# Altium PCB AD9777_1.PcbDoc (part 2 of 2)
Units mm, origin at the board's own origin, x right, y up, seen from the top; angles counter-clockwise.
Board outline 148.59 x 134.62 mm, 4 copper layers (Top Layer, Ground, POwer, Bottom Layer), stack 0.778 mm thick; 277 components, 168 nets, 827 pads, 113 vias.
Unrouted connection lines stored in the file: 4.
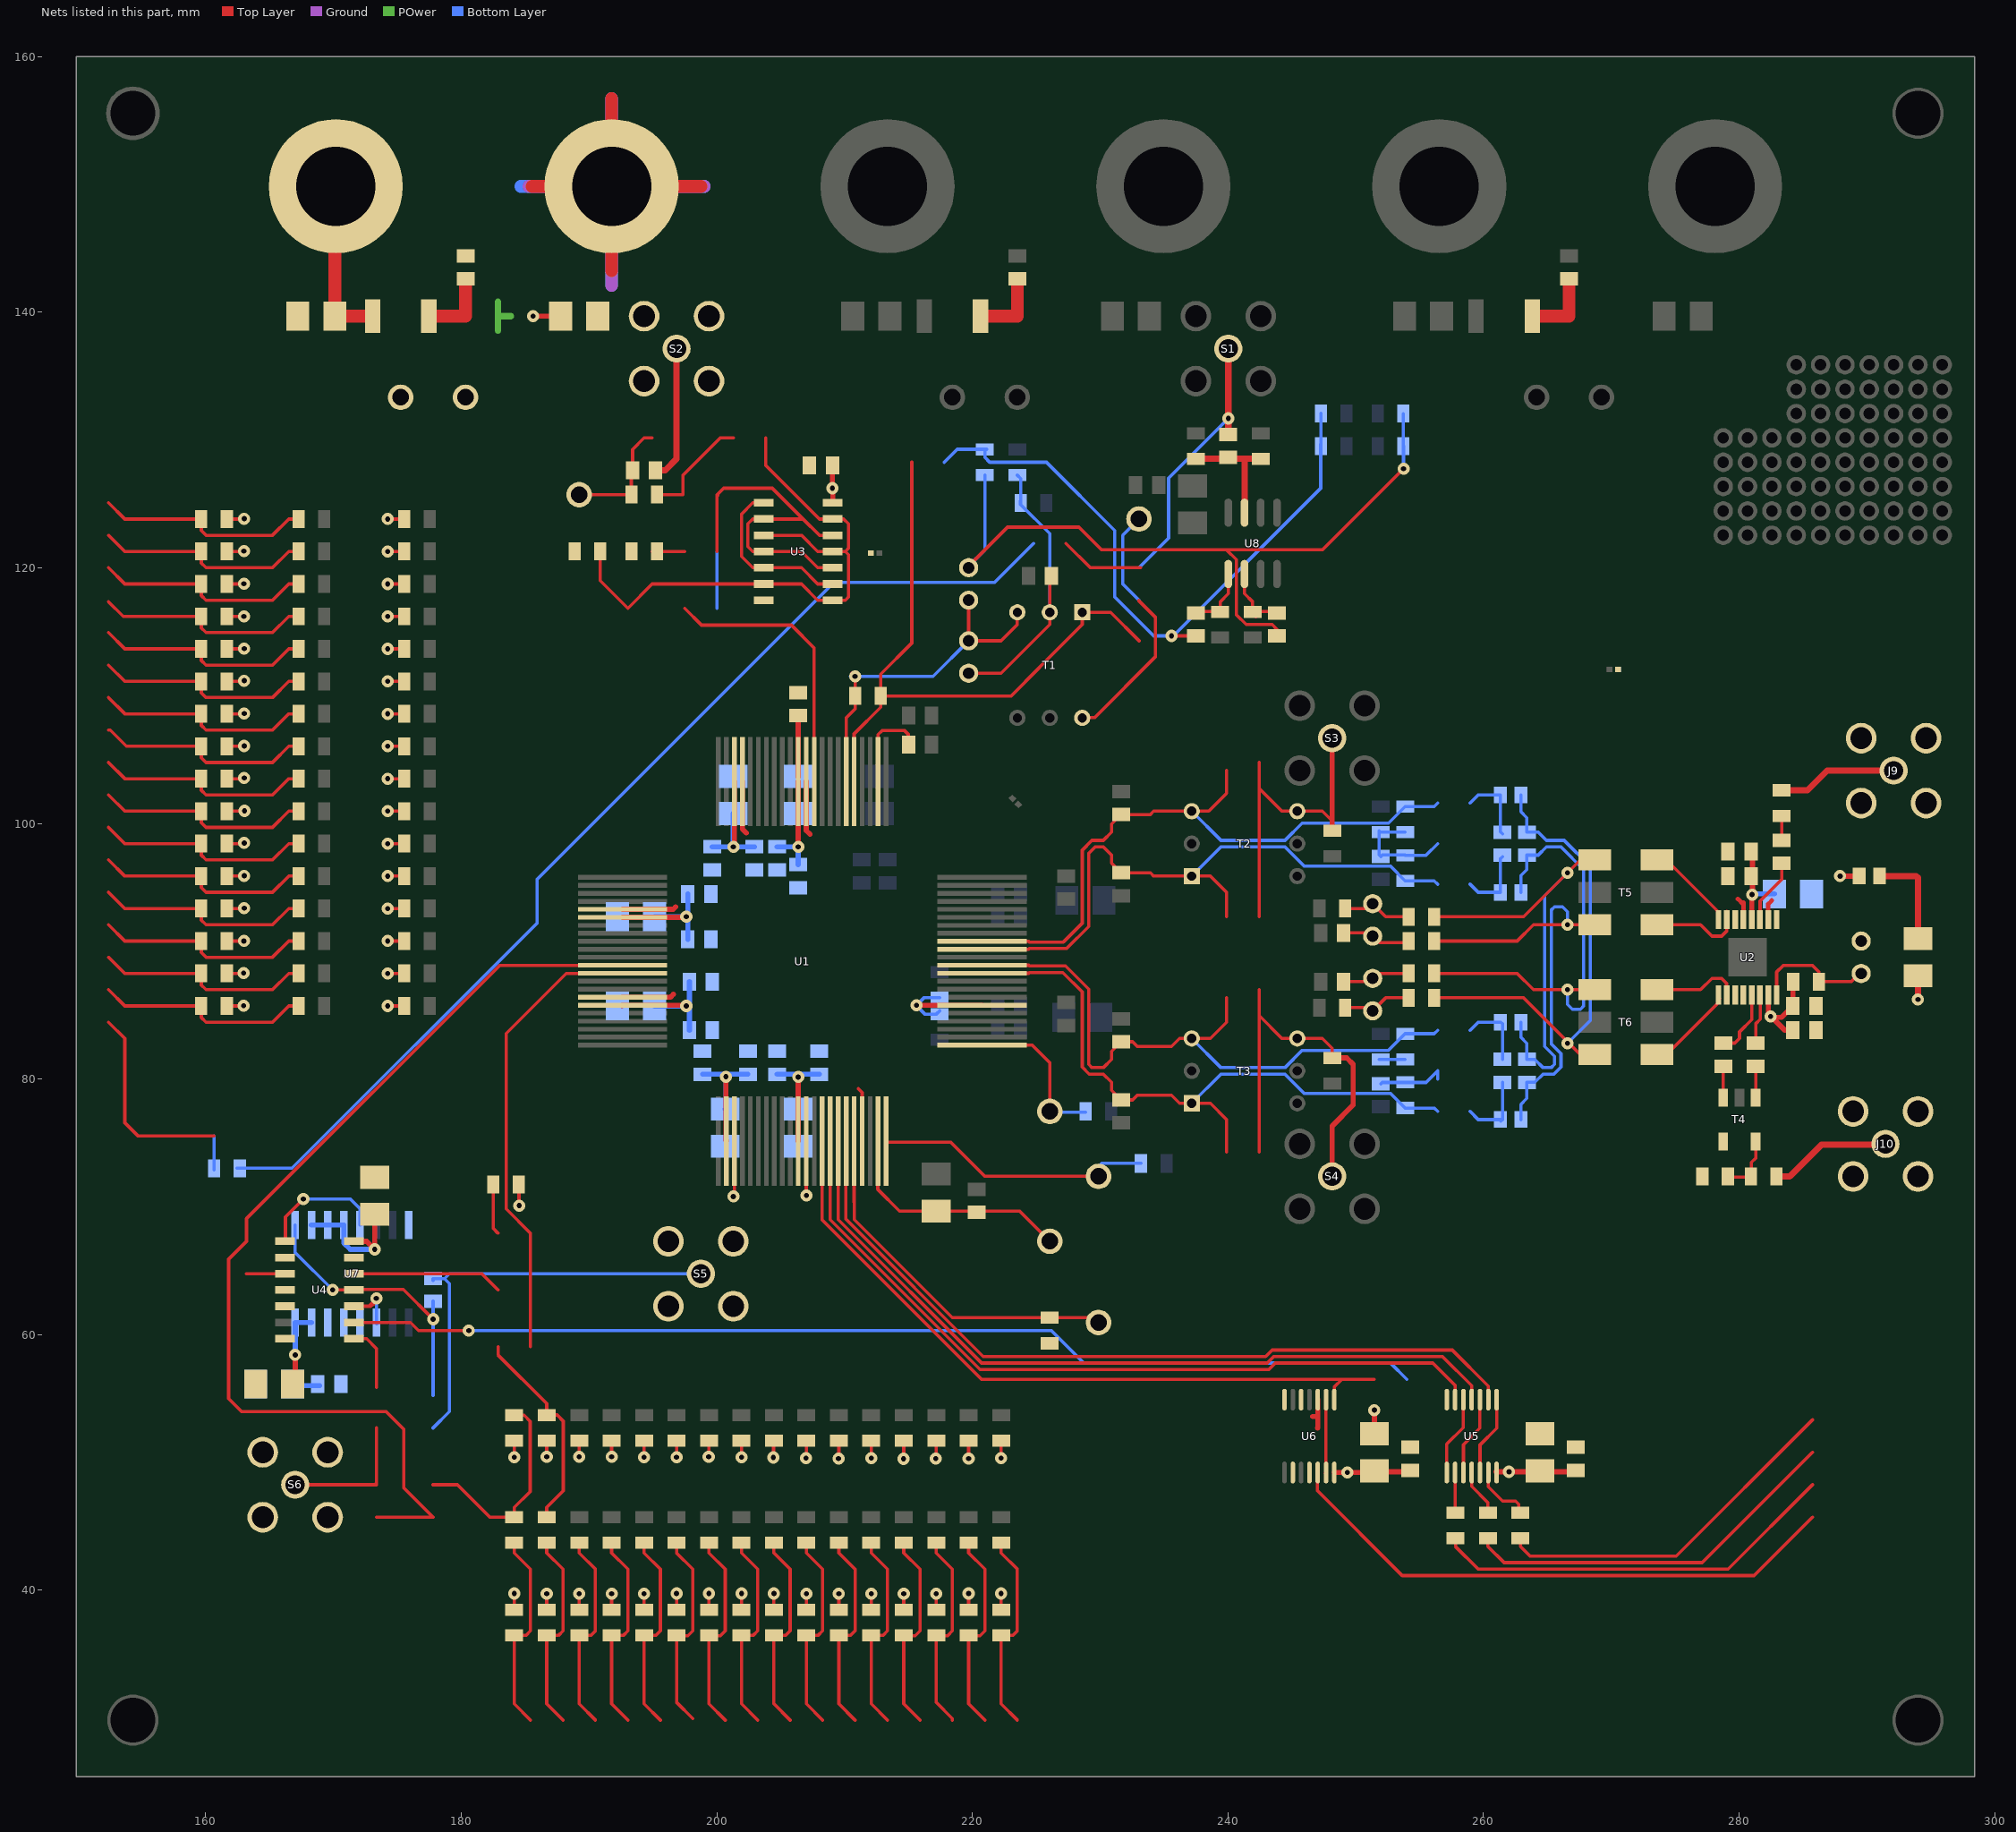
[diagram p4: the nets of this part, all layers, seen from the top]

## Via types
v1: diameter 0.95, hole 0.4, Top Layer to Bottom Layer, 112 vias
v2: diameter 0.95, hole 0.4, Top Layer to Bottom Layer, tented bottom, 1 vias

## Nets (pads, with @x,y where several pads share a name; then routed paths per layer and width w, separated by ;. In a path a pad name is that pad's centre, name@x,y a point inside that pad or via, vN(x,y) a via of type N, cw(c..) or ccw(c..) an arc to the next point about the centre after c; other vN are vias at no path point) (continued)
DGND: C5.2 C6.2 C7.2 C8.2 C9.2 C10.2 C21.2 C22.2 C23.2 C24.2 C25.2 C26.2 C30.2@173.228,72.316 C31.2 C33.2 C34.2 C36.2 C37.2 C38.2 C39.2 C40.2 C41.2 C43.2 C44.2 C50.1 C51.1 C52.2 C53.2 C65.2 C66.2 C67.2 J5.1 JP44.1 R6.1 R13.1@161.655,123.825 R14.1@161.655,121.285 R18.1@161.655,118.745 R25.1 R27.1 R29.1 R31.1 R38.1 R39.2 R40.1 R41.1 R44.1 R46.1 R47.1 R49.1 R51.1 R52.1 R53.1 R54.1 R55.2 R56.2 R57.2 R58.2 R59.2 R60.2 R61.2 R62.2 R63.2 R64.2 R65.2 R66.2 R67.2 R68.2 R69.2 R70.2 R71.1 R72.1 R73.1 R74.1 R75.1 R76.1 R77.1 R78.1 R79.1 R80.1 R81.1 R82.1 R83.1 R84.1 R85.1 R86.1 R90.2 R91.2 R92.2 R93.2 R94.2 R95.2 R96.2 R97.2 R98.2 R99.2 R100.2 R101.2 R102.2 R103.2 R104.2 R105.2 S2.2 S5.2 S6.2 TP3.1 U1.11 U1.19 U1.27 U1.38 U1.47 U1.56 U1.63 U3.7 U4.2 U4.4 U4.5 U4.7 U4.10 U4.13 U5.7 U6.3 U6.5 U6.7 U6.9 U6.11 U7.8 U7.11 U7.12 U7.13 U7.14 | length 209.2
  Top Layer w0.254: R62.2@161.655,85.725 162.966,85.725 v1(162.966,85.75) ; R61.2@161.655,88.265 v1@162.941,88.265 ; R60.2@161.655,90.805 v1(162.992,90.805) ; R59.2@161.655,93.345 v1@162.992,93.345 ; R58.2@161.655,95.885 162.992,95.885 v1(163.017,95.91) ; R57.2@161.655,98.425 162.966,98.425 v1(163.017,98.476) ; R56.2@161.655,100.965 163.017,100.965 v1(163.043,100.99) ; R55.2@161.655,103.505 162.966,103.505 v1(163.017,103.556) ; R41.1@161.655,106.045 162.992,106.045 v1(163.017,106.07) ; R31.1@161.655,108.585 162.992,108.585 v1(163.017,108.61) ; R29.1@161.655,111.125 163.017,111.125 v1(163.017,111.176) ; R27.1@161.655,113.665 162.992,113.665 v1(163.017,113.69) ; R25.1@161.655,116.205 v1(162.992,116.205) ; R18.1@161.655,118.745 162.966,118.745 v1(162.992,118.77) ; R14.1@161.655,121.285 162.966,121.285 v1(162.992,121.31) ; R13.1@161.655,123.825 162.992,123.825 v1(163.017,123.85) ; U4.10@171.602,62.255 172.771,62.255 v1(173.355,62.84) ; U4.10@171.61,62.23 172.898,62.23 172.98,62.313 173.057,62.313 ; 173.145,62.401 173.145,62.478 v1@173.317,62.649 ; v1(174.244,85.725) R70.2@175.53,85.725 ; v1(174.244,88.265) R69.2@175.53,88.265 ; v1(174.244,90.805) R68.2@175.53,90.805 ; v1(174.244,93.345) R67.2@175.53,93.345 ; v1(174.244,95.885) R66.2@175.53,95.885 ; v1(174.244,98.425) R65.2@175.53,98.425 ; v1(174.244,100.965) R64.2@175.53,100.965 ; v1(174.244,103.505) R63.2@175.53,103.505 ; v1(174.244,106.045) R54.1@175.53,106.045 ; v1(174.244,108.585) R53.1@175.53,108.585 ; v1(174.244,111.125) R52.1@175.53,111.125 ; v1(174.244,113.665) R51.1@175.53,113.665 ; v1(174.244,116.205) R49.1@175.53,116.205 ; v1(174.244,118.745) R47.1@175.53,118.745 ; v1(174.244,121.285) R46.1@175.53,121.285 ; v1(174.244,123.825) R44.1@175.53,123.825 ; R71.1@184.15,38.465 v1@184.15,39.726 ; v1(184.15,50.419) R79.1@184.15,51.705 ; R39.2@184.515,71.755 184.515,70.12 v1(184.531,70.104) ; v1@186.639,50.444 186.69,50.495 R80.1@186.69,51.705 ; R72.1@186.69,38.465 v1(186.69,39.726) v1@186.69,39.802 ; R73.1@189.23,38.465 v1(189.23,39.726) ; v1(189.23,50.444) R81.1@189.23,51.705 ; R74.1@191.77,38.465 v1@191.77,39.675 ; v1(191.77,50.444) R82.1@191.77,51.705 ; v1@194.259,39.726 194.31,39.675 R75.1@194.31,38.465 ; v1@194.31,50.444 R83.1@194.31,51.705 ; R76.1@196.85,38.465 v1(196.85,39.751) ; v1@196.85,50.394 v1(196.85,50.419) R84.1@196.85,51.705 ; R77.1@199.39,38.465 v1(199.39,39.751) ; v1@199.39,50.495 R85.1@199.39,51.705 R85.1@199.39,51.73 ; v1@201.32,70.891 201.375,70.891 U1.47@201.375,75.16 ; R78.1@201.93,38.465 v1(201.93,39.751) ; v1(201.93,50.419) R86.1@201.93,51.705 ; v1@204.445,50.419 R98.2@204.445,51.68 ; R90.2@204.47,38.465 v1(204.47,39.751) ; v1@207,70.876 U1.56@207,75.16 ; R91.2@207.01,38.465 v1(207.01,39.726) v1@207.01,39.751 ; v1@207.01,50.368 R99.2@207.01,51.705 ; v2(209.525,50.317) 209.55,50.343 R100.2@209.55,51.705 ; R92.2@209.55,38.465 v1(209.55,39.726) ; 211.074,79.248 211.375,78.947 U1.63@211.375,75.16 U1.63@211.379,75.156 ; R93.2@212.09,38.465 v1(212.09,39.726) ; v1(212.09,50.343) R101.2@212.09,51.705 ; R94.2@214.63,38.465 v1(214.63,39.726) ; v1@214.63,50.267 R102.2@214.63,51.705 ; R95.2@217.17,38.465 v1(217.17,39.726) ; v1@217.17,50.317 R103.2@217.17,51.705 ; R96.2@219.71,38.465 v1@219.71,39.726 ; v1(219.71,50.317) R104.2@219.71,51.705 ; R97.2@222.25,38.465 v1@222.25,39.726 ; v1(222.25,50.343) R105.2@222.25,51.705
  Top Layer w0.4: U1.38@192.625,86.41 196.367,86.41 196.596,86.639 ; U1.27@192.625,93.285 196.587,93.285 196.774,93.472 ; U1.19@202,103.285 202,99.574 202.311,99.263 ; U1.11@207,103.285 207,99.451 207.289,99.162 ; 246.634,53.594 247.03,53.594 ; 247.015,52.705 247.03,52.72 247.03,53.594 ; U6.3@247.03,54.92 247.03,53.594 ; C43.2@251.46,52.25 v1(251.46,54.102)
  Top Layer w1: 185.547,149.86 J5.1@191.77,149.86 ; 191.77,143.256 J5.1@191.77,149.86 ; 191.77,156.718 J5.1@191.77,149.86 ; 198.755,149.86 J5.1@191.77,149.86
  Ground w1: 185.293,149.86 J5.1@191.77,149.86 ; 191.77,142.113 J5.1@191.77,149.86 ; 191.77,156.718 J5.1@191.77,149.86 ; 199.009,149.86 J5.1@191.77,149.86
  Bottom Layer w0.254: v1(173.355,62.84) U7.11@173.355,60.96 173.355,60.884 U7.11@173.38,60.858
  Bottom Layer w1: 184.658,149.86 J5.1@191.77,149.86 ; 191.77,142.113 J5.1@191.77,149.86 ; 191.77,156.718 J5.1@191.77,149.86 ; 199.009,149.86 J5.1@191.77,149.86
  other v1: 191.77,39.726 194.31,39.726 184.15,39.751 219.71,39.751 222.25,39.751 214.605,50.292 217.145,50.317 206.985,50.343 204.419,50.394 194.31,50.419 186.69,50.444 199.365,50.444 201.295,70.815 207.01,70.891 162.966,88.29 163.017,93.37
DGND2: C28.2 C32.2 C35.2 C72.2 C75.2 C78.2 J9.2 J10.2 JP7.2 JP18.2 JP21.2 R30.1 T4.5 U2.3 U2.4 U2.9 U2.10 U2.13 U2.14 | length 5.1
  Top Layer w0.35: 279.908,94.107 280.345,93.67 U2.13@280.345,92.485 ; 280.314,93.828 280.345,93.797 ; U2.10@282.295,92.485 282.295,93.7 282.575,93.98
  Top Layer w0.5: v1(294.005,86.233) C28.2@294.005,87.905
DVDD: C5.1 C6.1 C7.1 C8.1 C9.1 C10.1 C21.1 C22.1 C23.1 C24.1 C25.1 C26.1 C30.1@173.228,69.416 C31.1 C33.1 C34.1 C36.1 C37.1 C38.1 C39.1 C40.1 C41.1 C43.1 C44.1 C50.2 C51.2 C52.1 C53.1 C66.1 TP2.1 U1.12 U1.20 U1.28 U1.39 U1.46 U1.55 U3.14 U4.14 U5.14 U6.14 U7.2 U7.3 U7.4 U7.15 U7.16 | length 113.2
  Top Layer w0.4: C31.1@166.878,56.134 167.005,56.261 v1(167.005,58.42) ; U4.14@171.61,67.31 172.593,67.31 v1(173.228,66.675) ; C30.1@173.228,69.416 173.228,66.7 v1@173.253,66.675 ; v1@185.674,139.7 C66.1@187.78,139.7 ; U1.39@192.59,85.75 U1.39@192.625,85.785 197.628,85.785 v1@197.637,85.776 ; U1.28@192.625,92.66 197.486,92.66 v1@197.51,92.685 ; v1@200.711,79.883 200.711,75.199 U1.46@200.75,75.16 ; v1@201.371,98.577 201.375,98.581 U1.20@201.375,103.285 ; U1.55@206.375,75.16 v1(206.375,80.162) ; U1.12@206.375,103.285 v1(206.375,98.171) 206.375,98.12 v1@206.4,98.095 ; U1.12@206.375,103.632 C33.1@206.375,108.447 ; v1(209.042,126.238) 209.042,128.132 C53.1@209.18,128.27 ; U3.14@209.075,125.095 v1@209.075,126.238 ; U6.14@248.33,49.22 249.347,49.22 v1(249.352,49.225) 251.663,49.225 251.714,49.276 C50.2@254.508,49.276 ; U5.14@260.985,49.276 v1(262.001,49.276) C51.2@267.335,49.276
  POwer w0.5: 182.88,138.557 182.88,139.7 ; 182.88,140.843 182.88,139.7 ; 183.896,139.7 182.88,139.7
  Bottom Layer w0.4: U7.15@168.275,60.96 U7.16@167.005,60.96 v1(167.005,58.42) 167.005,56.134 166.878,56.007 C34.1@168.91,56.007 ; U7.2@168.275,68.58 U7.3@169.545,68.58 U7.4@170.815,68.58 170.815,67.183 171.323,66.675 v1(173.228,66.675) ; C5.1@195.125,85.725 v1@197.485,85.725 ; C8.1@195.125,92.71 197.46,92.71 v1@197.51,92.761 ; v1@197.474,85.587 197.485,85.598 v1@197.485,85.725 ; v1@197.474,85.863 v1@197.485,85.852 ; C38.1@197.728,90.932 197.728,92.594 v1(197.612,92.71) 197.728,92.826 C24.1@197.728,94.488 ; C21.1@197.855,83.82 197.855,85.482 v1(197.612,85.725) ; C39.1@197.855,87.63 197.855,85.968 v1(197.612,85.725) ; C41.1@198.882,80.38 200.417,80.38 v1@200.66,80.137 ; C36.1@199.644,98.182 201.284,98.182 v1(201.295,98.171) 201.306,98.182 C25.1@202.946,98.182 ; C6.1@200.66,77.65 200.711,77.701 v1@200.711,80.137 ; v1@200.903,80.38 C22.1@202.438,80.38 ; v1@201.295,98.552 C9.1@201.295,100.785 ; C23.1@204.724,80.38 v1@206.132,80.38 ; C37.1@204.724,98.182 206.364,98.182 v1(206.375,98.171) ; C7.1@206.375,77.65 206.375,80.137 206.618,80.38 C40.1@208.026,80.38 ; C26.1@206.375,96.785 v1@206.375,98.12 ; C10.1@206.375,100.785 v1(206.375,98.171) ; v1@206.4,98.095 v1@206.375,98.12 ; v1@197.485,85.725 v1@197.485,85.852 ; v1@197.485,85.852 v1(197.612,85.725) ; v1@206.375,98.12 v1(206.375,98.171)
  other v1: 200.711,80.188 185.623,139.7
DVDD_IN: C65.1 J8.1 L3.2 | length 13
  Top Layer w1: J8.1@170.106,149.786 C65.1@170.106,139.7 L3.2@172.974,139.7
GND: 
IBB_N: T6.6 U2.2 | length 6.4
  Top Layer w0.254: T6.6@274.07,86.995 276.987,86.995 277.876,87.884 278.638,87.884 279.019,87.503 279.019,86.611 U2.2@279.045,86.585
IBB_P: T6.4 U2.1 | length 7.1
  Top Layer w0.254: T6.4@274.066,81.788 274.066,81.915 T6.4@274.07,81.915 ; T6.4@274.07,81.919 T6.4@274.07,81.915 ; U2.1@278.395,86.585 U2.1@278.395,86.244 ; U2.1@278.415,86.565 278.415,86.361 278.463,86.312 U2.1@278.395,86.244 ; T6.4@274.07,81.915 274.32,81.915 278.395,85.99 U2.1@278.395,86.244
IOUTA1_N: C57.2 R10.2 T2.1 U1.79 | length 51.4
  Top Layer w0.254: U1.79@220.75,90.16 224.409,90.16 224.468,90.219 227.379,90.219 229.108,91.948 229.108,97.663 229.616,98.171 230.251,98.171 230.897,97.525 230.897,96.901 C57.2@231.648,96.15 ; C57.2@231.278,95.885 231.532,96.139 233.934,96.139 234.188,95.885 235.966,95.885 T2.1@237.043,95.885 ; T2.1@237.109,95.885 238.633,95.885 239.903,94.615 239.903,92.71
  Bottom Layer w0.254: T2.1@237.17,95.885 239.456,98.171 244.465,98.171 245.968,96.668 252.725,96.668 R10.2@253.873,95.52 256.143,95.52 256.413,95.25
IOUTA1_P: C56.2 R9.2 T2.3 U1.80 | length 50.9
  Top Layer w0.254: U1.80@219.939,90.78 U1.80@219.964,90.805 ; U1.80@220.75,90.785 224.409,90.785 224.467,90.727 227.125,90.727 228.6,92.202 228.6,97.917 229.362,98.679 230.251,98.679 230.897,99.325 230.897,99.949 C56.2@231.648,100.7 233.923,100.7 234.188,100.965 235.966,100.965 T2.3@237.17,100.965 238.506,100.965 239.903,102.362 239.903,104.14
  Bottom Layer w0.254: T2.3@237.17,100.965 239.456,98.679 244.465,98.679 245.818,100.032 252.575,100.032 R9.2@253.873,101.33 256.143,101.33 256.413,101.6
IOUTA2_N: C59.2 R12.2 T3.1 U1.76 | length 52
  Top Layer w0.254: U1.76@220.75,88.285 224.409,88.285 224.468,88.344 227.076,88.344 228.6,86.82 228.6,80.943 229.152,80.391 230.251,80.391 230.897,79.745 230.897,79.121 C59.2@231.648,78.37 232.537,78.37 232.907,78.74 235.585,78.74 236.22,78.105 T3.1@237.17,78.105 238.633,78.105 239.903,76.835 239.903,74.295
  Bottom Layer w0.254: T3.1@237.17,78.105 239.456,80.391 244.465,80.391 245.968,78.888 252.725,78.888 R12.2@253.873,77.74 ; R12.2@253.873,77.724 256.159,77.724 256.413,77.47
IOUTA2_P: C58.2 R11.2 T3.3 U1.77 | length 51.4
  Top Layer w0.254: U1.77@220.75,88.91 224.409,88.91 224.467,88.852 227.286,88.852 229.108,87.03 229.108,81.153 229.362,80.899 230.251,80.899 230.897,81.545 230.897,82.169 C58.2@231.648,82.92 232.537,82.92 232.907,82.55 235.585,82.55 236.22,83.185 T3.3@237.17,83.185 238.633,83.185 239.903,84.455 239.903,86.36
  Bottom Layer w0.254: T3.3@237.17,83.185 239.456,80.899 244.465,80.899 245.818,82.252 252.575,82.252 R11.2@253.873,83.55 256.143,83.55 256.413,83.82
LOI_N: C77.2 U2.5 | length 5.9
  Top Layer w0.254: C77.2@278.765,82.815 279.665,82.815 280.035,83.185 280.035,83.693 281,84.658 281,87.147 U2.5@280.975,87.173 ; U2.5@280.975,87.224 U2.5@280.975,87.173 ; U2.5@281,87.198 U2.5@280.975,87.173
LOI_P: C76.2 U2.6 | length 4.6
  Top Layer w0.254: C76.2@281.305,82.804 C76.2@281.31,82.809 ; C76.2@281.305,82.815 281.305,84.328 281.661,84.684 U2.6@281.661,87.224
NetC4_1: C4.1 C16.1 TP10.1 U1.65 | length 23.8
  Top Layer w0.254: U1.65@212.598,75.565 212.598,71.374 214.302,69.67 C4.1@217.17,69.67 223.7,69.67 TP10.1@226.06,67.31 TP10.1@226.06,66.548 ; 212.625,71.474 U1.65@212.625,75.16
NetC13_2: C13.2 JP23.2 R2.2 R3.1 T1.2 | length 23.5
  Top Layer w0.254: JP23.2@219.71,111.76 222.25,111.76 226.06,115.57 T1.2@226.06,116.525 C13.2@226.06,119.38
  Bottom Layer w0.254: R3.1@223.52,127.254 223.79,126.984 R2.2@223.79,125.222 ; R2.2@223.774,125.222 223.774,124.968 226.06,122.682 T1.2@226.06,116.525
NetC27_2: C27.2 U1.2 | length 7.2
  Top Layer w0.254: U1.2@212.625,103.285 212.625,106.961 212.928,107.264 214.706,107.264 214.986,106.985 214.986,106.121 C27.2@215.011,106.121
NetC29_1: C29.1 R5.2 TP14.1 | length 9.6
  Top Layer w0.254: TP14.1@189.23,125.73 R5.2@193.294,125.73 ; R5.2@193.31,125.73 193.31,127.524 C29.1@193.421,127.635 ; C29.1@193.41,127.635 193.41,129.275 194.31,130.175 194.945,130.175
NetC29_2: C29.2 S2.1 | length 10.8
  Top Layer w0.5: C29.2@195.21,127.635 195.961,127.635 196.85,128.524 S2.1@196.85,137.16 S2.1@196.85,137.287
NetC45_1: C45.1 S5.1 | length 34.1
  Bottom Layer w0.254: 177.8,52.705 179.07,53.975 179.07,64.008 178.689,64.389 ; C45.1@177.8,64.262 177.8,64.389 178.689,64.389 ; S5.1@198.755,64.77 S5.1@198.628,64.77 ; S5.1@199.009,65.151 S5.1@198.628,64.77 ; 178.689,64.389 179.07,64.77 S5.1@198.628,64.77
NetC45_2: C45.2 U4.11 U7.1 | length 22.5
  Top Layer w0.254: v1(169.926,63.5) U4.11@171.61,63.5 171.652,63.542 175.472,63.542 v1(177.8,61.214)
  Bottom Layer w0.254: U7.1@167.005,68.58 167.005,66.421 v1(169.926,63.5) ; 177.8,55.245 v1(177.8,61.214) C45.2@177.8,62.6 C45.2@177.8,62.611
NetC46_1: C46.1 S1.1 | length 27.8
  Top Layer w0.254: 227.33,121.92 229.235,120.015 233.172,120.015
  Top Layer w0.5: C46.1@240.03,130.44 v1(240.03,131.699) S1.1@240.03,137.033
  Bottom Layer w0.254: 233.045,120.015 235.356,122.326 235.356,127.025 v1(240.03,131.699)
NetC46_2: C46.2 R4.1 R13.2@242.57,128.54 U8.7 | length 9.3
  Top Layer w0.5: R4.1@237.49,128.524 237.506,128.54 241.3,128.54 ; U8.7@241.3,124.32 241.3,128.54 ; R13.2@242.57,128.54 241.3,128.54
NetC47_1: C47.1 R14.2@241.935,116.57 U8.2 | length 6
  Top Layer w0.254: U8.2@241.3,119.634 U8.2@241.3,119.52 241.3,117.983 241.935,117.348 241.935,116.443 242.189,116.189 242.189,116.586 C47.1@243.967,116.586
NetC47_2: C47.2 JP42.1 R19.2 R20.1 R21.1 | length 60.6
  Top Layer w0.254: JP42.1@219.71,120.015 219.71,120.142 222.758,123.19 228.346,123.19 230.124,121.412 239.903,121.412 ; C47.2@243.84,114.67 243.84,115.189 243.459,115.57 241.427,115.57 240.665,116.332 240.665,120.65 239.903,121.412 ; v1(253.746,127.762) 247.396,121.412 239.903,121.412
  Bottom Layer w0.254: JP42.1@219.71,119.888 JP42.1@219.71,120.015 219.71,120.142 220.98,121.412 R19.2@220.98,127.27 ; R21.1@253.73,129.54 R20.1@253.73,132.064 ; v1(253.746,127.762) R21.1@253.746,129.54
NetC48_1: C48.1 R18.2@239.395,116.57 U8.1 | length 5.7
  Top Layer w0.254: C48.1@237.125,116.189 237.522,116.586 239.395,116.586 239.395,117.348 240.03,117.983 U8.1@240.03,119.52 U8.1@240.03,119.634
NetC48_2: C48.2 R19.1 R22.1 R24.1 | length 54.4
  Top Layer w0.254: v1(235.585,114.681) C48.2@237.49,114.681
  Bottom Layer w0.254: 217.805,128.27 218.805,129.27 ; R19.1@221.107,129.286 218.821,129.286 218.805,129.27 ; v1(235.585,114.681) 234.188,114.681 231.14,117.729 231.14,122.936 225.806,128.27 221.361,128.27 220.98,128.651 R19.1@220.98,129.27 218.805,129.27 ; v1@235.648,114.617 247.269,126.238 R22.1@247.269,129.667 ; R22.1@247.285,129.429 R22.1@247.285,129.54 R24.1@247.285,132.08
NetC54_1: C54.1 L5.2 | length 5.8
  Bottom Layer w0.254: 258.953,101.6 259.588,102.235 L5.2@261.328,102.235 261.328,99.352 C54.1@261.493,99.187
NetC54_2: C54.2 L4.2 | length 5.5
  Bottom Layer w0.254: 258.953,95.25 259.588,94.615 L4.2@261.328,94.615 261.328,97.244 C54.2@261.493,97.409
NetC55_1: C55.1 L7.2 | length 5.6
  Bottom Layer w0.254: 258.953,83.82 259.588,84.455 L7.2@261.328,84.455 ; L7.2@261.366,84.455 261.493,84.328 C55.1@261.493,81.545
NetC55_2: C55.2 L6.2 | length 5.7
  Bottom Layer w0.254: 258.953,77.47 259.588,76.835 L6.2@261.328,76.835 ; L6.2@261.366,76.708 261.493,76.835 C55.2@261.493,79.745
NetC67_1: C67.1 L3.1 | length 5.4
  Top Layer w1: L3.1@177.8,139.7 180.34,139.7 C67.1@180.34,142.61
NetC68_1: C68.1 L2.1 | length 5.7
  Top Layer w1: L2.1@263.906,139.7 266.7,139.7 C68.1@266.7,142.61
NetC69_1: C69.1 L1.1 | length 5.8
  Top Layer w1: L1.1@220.599,139.7 223.52,139.7 C69.1@223.52,142.61
NetC70_1: C70.1 R9.1 R10.1 R16.2 | length 9
  Bottom Layer w0.254: R10.1@253.873,97.52 255.508,97.52 256.413,98.425 ; R10.1@253.873,97.536 252.095,97.536 251.968,97.409 251.841,97.536 251.841,99.441 251.952,99.33 R16.2@251.968,99.33 R9.1@253.873,99.33
NetC71_1: C71.1 R12.1 | length 5.5
  Bottom Layer w0.254: C71.1@251.968,79.629 252.079,79.74 R12.1@253.873,79.74 255.508,79.74 256.413,80.645 256.413,80.01
NetC74_1: C74.1 U2.11 | length 4.7
  Top Layer w0.254: U2.11@281.645,92.485 281.645,93.939 283.337,95.631 C74.1@283.337,96.52
NetC74_2: C74.2 R23.1 | length 1.9
  Top Layer w0.254: C74.2@283.337,98.69 R23.1@283.337,100.6
NetC76_1: C76.1 T4.3 | length 2.5
  Top Layer w0.254: T4.3@281.305,78.486 C76.1@281.305,81.015 C76.1@281.305,81.026
NetC77_1: C77.1 T4.1 | length 2.7
  Top Layer w0.254: T4.1@278.765,78.359 C77.1@278.765,81.015 C77.1@278.765,81.026
NetC79_1: C79.1 JP19.1 R32.2 | length 5.4
  Top Layer w0.254: C79.1@249.058,91.44 251.079,91.44 JP19.1@251.333,91.186 251.841,90.678 R32.2@254.127,90.678
NetC80_2: C80.2 JP20.1 R35.2 | length 5.3
  Top Layer w0.254: C80.2@249.058,87.63 250.952,87.63 JP20.1@251.333,88.011 ; JP20.1@251.46,87.884 251.841,88.265 R35.2@254.127,88.265
NetJ1_1: R13.2@159.655,123.825 RP1.1 | length 17
  Top Layer w0.254: 152.4,125.095 153.67,123.825 R13.2@159.639,123.825 ; R13.2@159.655,123.825 159.655,122.92 160.02,122.555 165.227,122.555 166.497,123.825 RP1.1@167.259,123.825
NetJ1_3: R14.2@159.655,121.285 RP2.1 | length 16.8
  Top Layer w0.254: 152.4,122.555 153.67,121.285 R14.2@159.487,121.285 ; R14.2@159.655,121.285 159.655,120.38 160.02,120.015 165.227,120.015 166.497,121.285 RP2.1@167.259,121.285
NetJ1_5: R18.2@159.655,118.745 RP3.1 | length 16.9
  Top Layer w0.254: 152.4,120.015 153.67,118.745 R18.2@159.614,118.745 ; R18.2@159.655,118.745 159.655,117.84 160.02,117.475 165.227,117.475 166.497,118.745 RP3.1@167.259,118.745
NetJ1_7: R25.2 RP4.1 | length 17
  Top Layer w0.254: 152.4,117.348 153.543,116.205 R25.2@159.614,116.205 ; R25.2@159.655,116.205 159.655,115.3 160.02,114.935 165.227,114.935 166.497,116.205 RP4.1@167.275,116.205 RP4.1@167.386,116.205
NetJ1_9: R27.2 RP5.1 | length 17.1
  Top Layer w0.254: 152.4,114.935 153.67,113.665 R27.2@159.655,113.665 159.655,112.76 160.02,112.395 165.227,112.395 166.497,113.665 RP5.1@167.275,113.665 RP5.1@167.386,113.665
NetJ1_11: R29.2 RP6.1 | length 17
  Top Layer w0.254: 152.4,112.395 153.67,111.125 R29.2@159.655,111.125 159.655,110.22 160.02,109.855 165.227,109.855 166.497,111.125 RP6.1@167.259,111.125 ; RP6.1@167.275,111.125 RP6.1@167.335,111.125
NetJ1_13: R31.2 RP8.1 | length 17
  Top Layer w0.254: 152.4,109.855 153.67,108.585 R31.2@159.655,108.585 159.655,107.68 160.02,107.315 165.227,107.315 166.497,108.585 RP8.1@167.259,108.585 ; RP8.1@167.275,108.585 RP8.1@167.335,108.585
NetJ1_15: R41.2 RP10.1 | length 16.8
  Top Layer w0.254: 152.4,107.315 152.527,107.315 153.797,106.045 R41.2@159.537,106.045 ; R41.2@159.655,106.045 159.655,105.14 160.02,104.775 165.227,104.775 166.497,106.045 RP10.1@167.259,106.045
NetJ1_17: R55.1 RP11.1 | length 17.1
  Top Layer w0.254: 152.4,104.775 153.67,103.505 R55.1@159.655,103.505 159.655,102.6 160.02,102.235 165.227,102.235 166.497,103.505 RP11.1@167.275,103.505 RP11.1@167.386,103.505
NetJ1_19: R56.1 RP12.1 | length 17
  Top Layer w0.254: 152.4,102.235 153.67,100.965 R56.1@159.537,100.965 ; R56.1@159.655,100.965 159.655,100.06 160.02,99.695 165.227,99.695 166.497,100.965 RP12.1@167.275,100.965 RP12.1@167.386,100.965
NetJ1_21: R57.1 RP13.1 | length 17
  Top Layer w0.254: 152.4,99.695 153.67,98.425 R57.1@159.655,98.425 159.655,97.52 160.02,97.155 165.227,97.155 166.497,98.425 RP13.1@167.259,98.425 ; RP13.1@167.275,98.425 RP13.1@167.335,98.425
NetJ1_23: R58.1 RP14.1 | length 16.9
  Top Layer w0.254: 152.4,97.155 153.67,95.885 R58.1@159.588,95.885 ; R58.1@159.655,95.885 159.655,94.98 160.02,94.615 165.227,94.615 166.497,95.885 RP14.1@167.259,95.885
NetJ1_25: R59.1 RP15.1 | length 17.1
  Top Layer w0.254: 152.4,94.615 153.67,93.345 R59.1@159.655,93.345 159.655,92.44 160.02,92.075 165.227,92.075 166.497,93.345 RP15.1@167.259,93.345 ; RP15.1@167.275,93.345 RP15.1@167.361,93.345
NetJ1_27: R60.1 RP16.1 | length 17
  Top Layer w0.254: 152.4,92.075 153.67,90.805 R60.1@159.512,90.805 ; R60.1@159.655,90.805 159.655,89.9 160.02,89.535 165.227,89.535 166.497,90.805 RP16.1@167.275,90.805 RP16.1@167.386,90.805
NetJ1_29: R61.1 RP17.1 | length 17.1
  Top Layer w0.254: 152.4,89.535 153.67,88.265 R61.1@159.639,88.265 ; R61.1@159.655,88.265 159.655,87.36 160.02,86.995 165.227,86.995 166.497,88.265 RP17.1@167.275,88.265 RP17.1@167.386,88.265
NetJ1_31: R62.1 RP18.1 | length 17.1
  Top Layer w0.254: 152.4,86.995 153.67,85.725 R62.1@159.614,85.725 ; R62.1@159.655,85.725 159.655,84.82 160.02,84.455 165.227,84.455 166.497,85.725 RP18.1@167.275,85.725 RP18.1@167.386,85.725
NetJ1_33: R15.1 | length 18.5
  Top Layer w0.254: 152.4,84.455 153.67,83.185 153.67,76.581 154.686,75.565 160.655,75.565
  Bottom Layer w0.254: R15.1@160.655,72.898 160.655,75.565
NetJ2_1: R71.2 RP19.1 | length 15.9
  Top Layer w0.254: RP19.1@184.125,43.739 RP19.1@184.15,43.739 ; R71.2@184.15,36.373 184.15,31.115 185.42,29.845 ; R71.2@184.15,36.465 185.055,36.465 185.42,36.83 185.42,41.656 184.15,42.926 RP19.1@184.15,43.72
NetJ2_3: R72.2 RP20.1 | length 15.9
  Top Layer w0.254: R72.2@186.69,36.424 186.69,31.115 187.96,29.845 ; R72.2@186.69,36.465 187.595,36.465 187.96,36.83 187.96,41.656 186.69,42.926 RP20.1@186.69,43.72
NetJ2_5: R73.2 RP21.1 | length 16
  Top Layer w0.254: R73.2@189.23,36.449 189.23,31.115 190.5,29.845 ; R73.2@189.23,36.465 190.135,36.465 190.5,36.83 190.5,41.656 189.23,42.926 RP21.1@189.23,43.72
NetJ2_7: R74.2 RP22.1 | length 16
  Top Layer w0.254: R74.2@191.77,36.449 191.77,31.115 193.04,29.845 ; R74.2@191.77,36.465 192.675,36.465 193.04,36.83 193.04,41.656 191.77,42.926 RP22.1@191.77,43.72
NetJ2_9: R75.2 RP23.1 | length 15.9
  Top Layer w0.254: R75.2@194.31,36.347 194.31,31.115 195.58,29.845 ; R75.2@194.31,36.465 195.215,36.465 195.58,36.83 195.58,41.656 194.31,42.926 RP23.1@194.31,43.72
NetJ2_11: R76.2 RP24.1 | length 15.8
  Top Layer w0.254: RP24.1@196.85,43.72 196.85,42.926 198.12,41.656 198.12,36.83 197.739,36.449 196.85,36.449 196.85,31.242 198.12,29.972
NetJ2_13: R77.2 RP25.1 | length 16
  Top Layer w0.254: RP25.1@199.39,43.72 199.39,42.926 200.66,41.656 200.66,36.83 200.279,36.449 199.39,36.449 199.39,31.115 200.66,29.845
NetJ2_15: R78.2 RP26.1 | length 16
  Top Layer w0.254: RP26.1@201.93,43.72 201.93,42.926 203.2,41.656 203.2,36.83 202.835,36.465 R78.2@201.93,36.465 201.93,31.115 203.2,29.845
NetJ2_17: R90.1 RP27.1 | length 16
  Top Layer w0.254: RP27.1@204.47,43.72 204.47,42.926 205.74,41.656 205.74,36.83 205.375,36.465 R90.1@204.47,36.465 204.47,31.115 205.74,29.845
NetJ2_19: R91.1 RP28.1 | length 15.9
  Top Layer w0.254: R91.1@207.01,36.398 207.01,31.115 208.28,29.845 ; R91.1@207.01,36.465 207.915,36.465 208.28,36.83 208.28,41.656 207.01,42.926 RP28.1@207.01,43.72
NetJ2_21: R92.1 RP29.1 | length 15.9
  Top Layer w0.254: R92.1@209.55,36.347 209.55,31.115 210.82,29.845 ; R92.1@209.55,36.465 210.455,36.465 210.82,36.83 210.82,41.656 209.55,42.926 RP29.1@209.55,43.72
NetJ2_23: R93.1 RP30.1 | length 15.8
  Top Layer w0.254: R93.1@212.09,36.271 212.09,31.115 213.36,29.845 ; R93.1@212.09,36.465 212.995,36.465 213.36,36.83 213.36,41.656 212.09,42.926 RP30.1@212.09,43.72
NetJ2_25: R94.1 RP31.1 | length 15.9
  Top Layer w0.254: R94.1@214.63,36.424 214.63,31.115 215.9,29.845 ; R94.1@214.63,36.449 215.519,36.449 215.9,36.83 215.9,41.656 214.63,42.926 RP31.1@214.63,43.72
NetJ2_27: R95.1 RP32.1 | length 15.9
  Top Layer w0.254: R95.1@217.17,36.424 217.17,31.242 218.44,29.972 218.44,29.845 ; R95.1@217.17,36.449 218.059,36.449 218.44,36.83 218.44,41.656 217.17,42.926 RP32.1@217.17,43.72
NetJ2_29: R96.1 RP33.1 | length 15.8
  Top Layer w0.254: R96.1@219.71,36.297 219.71,31.115 220.98,29.845 ; R96.1@219.71,36.449 220.599,36.449 220.98,36.83 220.98,41.656 219.71,42.926 RP33.1@219.71,43.72
NetJ2_31: R97.1 RP34.1 | length 15.9
  Top Layer w0.254: R97.1@222.25,36.398 222.25,31.115 223.52,29.845 ; R97.1@222.25,36.465 223.155,36.465 223.52,36.83 223.52,41.656 222.25,42.926 RP34.1@222.25,43.72
NetJ9_1: J9.1 R23.2 | length 9.5
  Top Layer w0.254: J9.1@292.1,104.14 J9.1@292.227,104.14
  Top Layer w0.5: R23.2@283.337,102.6 285.353,102.6 286.893,104.14 J9.1@292.1,104.14
NetJ10_1: J10.1 R28.1 | length 9.7
  Top Layer w0.5: R28.1@282.94,72.39 283.972,72.39 286.461,74.879 291.541,74.879 J10.1@291.541,74.803
NetJP1_1: T1.6 TP15.1 | length 20.1
  Top Layer w0.254: T1.6@228.575,108.28 229.565,108.28 234.315,113.03 234.315,116.154 233.02,117.45
  Bottom Layer w0.254: 233.045,117.475 231.775,118.745 231.775,122.555 TP15.1@233.045,123.825
NetJP2_1: R15.2 | length 84.6
  Bottom Layer w0.254: R15.2@162.433,73.025 R15.2@162.671,73.025 166.751,73.025 185.928,92.202 185.928,95.631 209.169,118.872 221.742,118.872 224.79,121.92
NetJP4_2: R42.1 S3.1 T2.4 | length 26.1
  Top Layer w0.254: 242.443,92.71 242.443,102.743 ; 242.443,104.775 242.443,102.743 ; 248.158,100.203 247.396,100.965 244.221,100.965 242.443,102.743
  Top Layer w0.4: R42.1@248.158,99.441 248.158,100.203 S3.1@248.158,106.68
NetJP5_1: R79.2 RP19.2 | length 16.9
  Top Layer w0.254: 177.8,48.26 179.705,48.26 182.245,45.72 RP19.2@184.15,45.72 184.15,46.482 185.395,47.727 185.395,53.213 184.912,53.696 R79.2@184.15,53.696
NetJP5_2: U1.34 | length 79.2
  Top Layer w0.254: 173.355,45.72 177.8,45.72 175.514,48.006 175.514,52.578 174.117,53.975 162.814,53.975 161.798,54.991 161.798,65.913 163.195,67.31 163.195,69.088 183.007,88.9 U1.34@192.532,88.9
NetJP12_2: R40.2 U3.3 U3.6 U3.8 U3.11 U3.13 | length 47.4
  Top Layer w0.254: R40.2@190.881,121.285 190.881,118.999 193.04,116.84 194.945,118.745 U3.6@203.675,118.745 ; U3.3@203.675,122.555 206.629,122.555 207.899,121.285 U3.11@209.075,121.285 210.058,121.285 ; U3.6@203.708,118.745 206.629,118.745 207.899,117.475 U3.8@209.075,117.475 210.058,117.475 210.312,117.729 210.312,121.031 210.058,121.285 ; 203.835,130.175 203.835,128.016 208.026,123.825 U3.13@209.075,123.825 209.931,123.825 210.312,123.444 210.312,121.539 210.058,121.285
NetJP18_1: JP18.1 R26.1 U2.8 | length 9.9
  Top Layer w0.254: U2.8@282.945,86.585 282.945,88.381 283.464,88.9 285.75,88.9 286.258,88.392 286.258,87.63 288.798,87.63 JP18.1@289.56,88.392
NetJP19_2: JP19.2 R33.2 R34.1 | length 5.7
  Top Layer w0.254: R34.1@249.158,93.345 250.952,93.345 JP19.2@251.333,93.726 252.349,92.71 254.127,92.71 R33.2@254.254,92.583
NetJP20_2: JP20.2 R36.2 R37.1 | length 5.5
  Top Layer w0.254: R37.1@249.158,85.598 251.079,85.598 JP20.2@251.333,85.344 252.349,86.36 R36.2@254.127,86.36
NetJP22_2: R1.2 T1.1 U1.5 | length 51.2
  Top Layer w0.254: U1.5@210.744,103.276 210.718,103.276 210.744,103.302 210.744,107.01 212.836,109.102 R1.2@212.836,109.982 ; 215.265,128.27 215.265,114.122 212.836,111.693 R1.2@212.836,109.982 ; 225.234,112.204 228.6,115.57 T1.1@228.6,116.459 ; 225.247,112.192 223.037,109.982 R1.2@212.836,109.982 ; T1.1@228.6,116.525 230.82,116.525 233.045,114.3
NetJP23_1: JP23.1 JP42.2 R1.1 T1.3 U1.6 | length 27.9
  Top Layer w0.254: U1.6@210.134,103.276 210.125,103.286 210.125,108.271 210.82,108.966 v1(210.82,111.506) v1@210.566,111.76 ; JP23.1@219.71,114.173 JP23.1@219.71,114.3 ; JP42.2@219.71,117.475 JP23.1@219.71,114.3 ; T1.3@223.52,116.525 223.52,115.57 222.25,114.3 JP23.1@219.71,114.3
  Bottom Layer w0.254: v1@210.439,111.506 v1(210.82,111.506) 216.916,111.506 JP23.1@219.71,114.3
NetJP24_1: U3.2 U3.4 U3.10 U3.12 | length 33.2
  Top Layer w0.254: 200.025,121.285 200.025,125.603 200.088,125.666 ; 200.025,125.73 200.533,126.238 204.343,126.238 206.756,123.825 ; U3.10@209.042,120.015 207.899,120.015 206.629,121.285 U3.4@203.675,121.285 202.819,121.285 202.438,121.666 202.438,123.444 202.819,123.825 U3.2@203.675,123.825 206.756,123.825 ; U3.12@209.075,122.555 208.026,122.555 206.756,123.825
  Bottom Layer w0.254: 200.025,116.84 200.025,121.26
NetJP24_2: R5.1 | length 8.7
  Top Layer w0.254: R5.1@195.31,125.73 197.358,125.73 197.358,127.254 200.279,130.175 201.295,130.175
NetJP26_1: R80.2 RP20.2 | length 16.6
  Top Layer w0.254: 182.88,59.055 182.88,58.42 186.69,54.61 R80.2@186.69,53.705 R80.2@186.69,53.594 ; RP20.2@186.69,45.72 186.69,46.482 187.985,47.777 187.985,53.238 187.503,53.721 R80.2@186.715,53.721
NetJP26_2: U1.35 | length 36.4
  Top Layer w0.254: 185.42,59.055 185.42,67.945 183.515,69.85 183.515,83.566 188.214,88.265 U1.35@192.659,88.265
NetJP27_1: U4.3 | length 3
  Top Layer w0.254: 163.195,64.77 U4.3@166.21,64.77 U4.3@166.243,64.77
NetJP29_2: R43.1 S4.1 T3.4 | length 31.5
  Top Layer w0.254: 242.443,74.295 242.443,84.963 ; 242.443,86.995 242.443,84.963 ; R43.1@248.158,81.661 248.158,82.423 247.396,83.185 244.221,83.185 242.443,84.963
  Top Layer w0.4: S4.1@248.158,72.39 248.158,76.327 249.809,77.978 249.809,81.153 249.301,81.661 R43.1@248.158,81.661
NetJP31_1: U4.12 | length 11.8
  Top Layer w0.254: U4.12@171.577,64.77 U4.12@171.61,64.77 181.61,64.77 182.88,63.5
NetJP32_1: R39.1 | length 4
  Top Layer w0.254: R39.1@182.499,71.755 182.499,68.326 182.88,67.945
NetJP33_1: R38.2 | length 2.5
  Top Layer w0.254: R38.2@194.945,121.285 R38.2@195.31,121.285 197.485,121.285
NetJP39_2: U1.10 | length 22.2
  Top Layer w0.254: 197.485,116.84 198.806,115.519 205.842,115.519 207.62,113.741 U1.10@207.62,102.997
NetJP40_1: S6.1 | length 10.8
  Top Layer w0.254: S6.1@167.005,48.26 173.228,48.26 ; 173.355,48.26 173.228,48.26 ; 173.355,52.705 173.355,48.387 173.228,48.26
NetJP46_2: U4.8 | length 5.1
  Top Layer w0.254: U4.8@171.61,59.69 172.593,59.69 173.355,58.928 173.355,55.88
NetJP47_1: U4.9 | length 84.2
  Top Layer w0.254: U4.9@171.61,60.96 176.022,60.96 176.657,60.325 v1(180.594,60.325)
  Bottom Layer w0.254: v1(180.594,60.325) 226.187,60.325 228.727,57.785 252.73,57.785 254,56.515
NetP1_2: R50.1 | length 28.2
  Top Layer w0.254: R50.1@262.763,43.942 262.89,43.815 262.89,43.434 263.652,42.672 275.082,42.672 285.75,53.34
NetP1_3: R48.2 | length 30.1
  Top Layer w0.254: R48.2@260.223,43.942 260.35,43.815 260.35,43.434 261.62,42.164 277.114,42.164 285.75,50.8
NetP1_4: R45.2 | length 32
  Top Layer w0.254: R45.2@257.683,43.942 257.81,43.815 257.81,43.434 259.588,41.656 279.146,41.656 285.75,48.26
NetP1_5: U6.12 | length 44.9
  Top Layer w0.254: U6.12@247.015,49.276 247.015,47.777 253.644,41.148 281.178,41.148 285.75,45.72
NetR6_2: R6.2 TP11.1 U1.62 | length 36.6
  Top Layer w0.254: U1.62@210.744,78.308 210.744,70.383 210.769,70.358 ; U1.62@210.769,75.235 210.769,70.358 ; TP11.1@229.87,60.96 229.489,61.341 218.44,61.341 210.769,69.012 210.769,70.358
NetR7_2: R7.2 TP9.1 U1.66 | length 22.1
  Top Layer w0.254: U1.66@213.36,75.057 218.313,75.057 220.98,72.39 TP9.1@229.87,72.39
  Bottom Layer w0.254: TP9.1@229.108,72.39 230.124,73.406 R7.2@233.188,73.406
NetR8_2: R8.2 TP8.1 U1.67 | length 12.5
  Top Layer w0.254: U1.67@220.75,82.66 224.68,82.66 226.06,81.28 TP8.1@226.06,77.47
  Bottom Layer w0.254: TP8.1@226.06,77.419 R8.2@228.87,77.419
NetR11_1: R11.1 R17.2 | length 2
  Bottom Layer w0.254: R17.2@251.841,81.534 251.857,81.55 R17.2@251.968,81.55 R11.1@253.873,81.55
NetR28_2: R28.2 R30.2 T4.4 | length 5.7
  Top Layer w0.254: R30.2@279.07,72.339 280.924,72.339 280.975,72.39 280.975,73.482 281.305,73.812 281.305,74.168 ; T4.4@281.305,75.057 281.305,74.168 ; T4.4@281.305,75.12 281.305,74.168
NetR45_1: R45.1 U5.9 | length 3.4
  Top Layer w0.254: R45.1@257.683,45.958 R45.1@257.81,46.085 257.785,46.11 257.785,49.301 U5.9@257.759,49.327
NetR48_1: R48.1 U5.11 | length 3.9
  Top Layer w0.254: U5.11@259.08,49.327 U5.11@259.08,49.22 259.08,48.133 260.35,46.863 R48.1@260.35,46.085 R48.1@260.223,45.958
NetR50_2: R50.2 U5.13 | length 5
  Top Layer w0.254: U5.13@260.375,49.327 260.375,48.108 261.493,46.99 262.509,46.99 262.763,46.736 R50.2@262.763,45.958
NetR87_2: R87.2 R88.1 U1.72 | length 9.4
  Top Layer w0.4: v1@215.63,85.785 U1.72@220.75,85.785
  Bottom Layer w0.254: v1@215.595,85.776 216.281,85.09 217.186,85.09 R87.2@217.44,85.344 ; v1(215.621,85.776) 216.205,86.36 R88.1@217.44,86.36
NetU1_59: U1.59 U5.6 | length 65.2
  Top Layer w0.254: U1.59@208.864,78.181 208.864,69.012 220.599,57.277 243.205,57.277 243.713,57.785 256.032,57.785 257.785,56.032 U5.6@257.785,54.762
NetU1_60: U1.60 U5.4 | length 65.3
  Top Layer w0.254: U1.60@209.499,77.749 209.499,69.012 220.726,57.785 243.078,57.785 243.586,58.293 256.794,58.293 259.08,56.007 U5.4@259.08,54.92 259.08,54.864 259.055,54.839 U5.4@259.08,54.839
NetU1_61: U1.61 U5.2 | length 66.3
  Top Layer w0.254: U1.61@210.109,78.283 210.109,69.037 220.853,58.293 242.951,58.293 243.459,58.801 257.556,58.801 260.375,55.982 260.375,55.016 U5.2@260.35,54.991
NetU3_1: U3.1 U3.5 U3.9 | length 13.4
  Top Layer w0.254: U3.1@203.675,125.095 202.819,125.095 201.93,124.206 201.93,120.904 202.819,120.015 U3.5@203.675,120.015 206.629,120.015 207.899,118.745 U3.9@209.042,118.745
NetU4_1: U4.1 U7.5 | length 9.9
  Top Layer w0.254: U4.1@166.243,67.31 166.243,69.215 v1(167.64,70.612)
  Bottom Layer w0.254: v1(167.64,70.612) 171.323,70.612 172.085,69.85 U7.5@172.085,68.58
NetU5_1: U5.1 U5.12 | length 6.2
  Top Layer w0.254: U5.12@259.73,49.22 259.73,51.374 261.036,52.68 U5.1@261.036,54.915
NetU5_3: U5.3 U5.10 | length 6.4
  Top Layer w0.254: U5.10@258.43,49.22 258.43,51.395 259.715,52.68 U5.3@259.715,55.067
NetU5_5: U5.5 U5.8 | length 6.3
  Top Layer w0.254: U5.8@257.13,49.22 257.13,51.441 258.42,52.73 U5.5@258.42,54.991
NetU6_2: U6.2 U6.13 | length 5.8
  Top Layer w0.254: U6.13@247.65,49.149 247.68,49.179 U6.13@247.68,49.22 U6.2@247.68,54.92
O1_N: C73.2 L4.1 R35.1 T6.1 | length 34.6
  Top Layer w0.254: R35.1@256.143,88.265 262.636,88.265 263.906,86.995 T6.1@268.351,86.995
  Bottom Layer w0.254: L4.1@262.928,94.615 262.928,95.923 263.398,96.393 C73.2@263.398,97.525 264.287,97.525 264.933,98.171 266.065,98.171 267.843,96.393 267.843,85.725 267.589,85.471 266.954,85.471 266.573,85.852 v1(266.573,86.995)
O1_P: C73.1 L5.1 R36.1 T6.3 | length 37.6
  Top Layer w0.254: R36.1@256.143,86.36 263.144,86.36 263.779,85.725 ; 263.791,85.709 T6.3@267.585,81.915 ; T6.3@267.716,81.788 267.843,81.915 T6.3@268.22,81.915
  Bottom Layer w0.254: L5.1@262.928,102.235 262.928,100.927 263.398,100.457 C73.1@263.398,99.325 264.287,99.325 264.933,98.679 266.319,98.679 268.351,96.647 268.351,84.582 v1(266.573,82.804)
O2_N: C81.2 L6.1 R32.1 T5.3 | length 34
  Top Layer w0.254: R32.1@256.143,90.805 262.636,90.805 263.906,92.075 T5.3@268.224,92.075
  Bottom Layer w0.254: L6.1@262.928,76.835 262.928,78.016 263.398,78.486 C81.2@263.398,79.745 264.022,79.745 264.668,80.391 265.513,80.391 266.065,80.943 266.065,81.998 265.303,82.76 265.303,93.218 265.557,93.472 266.192,93.472 266.573,93.091 v1(266.573,92.075)
O2_P: C81.1 L7.1 R33.1 T5.1 | length 35.6
  Top Layer w0.254: R33.1@256.143,92.71 263.144,92.71 v1(266.573,96.139) 267.585,97.151 T5.1@267.585,97.155 ; T5.1@267.589,97.155 T5.1@268.22,97.155
  Bottom Layer w0.254: L7.1@262.928,84.455 262.928,83.274 263.398,82.804 C81.1@263.398,81.545 264.022,81.545 264.668,80.899 265.303,80.899 265.557,81.153 265.557,81.788 264.795,82.55 264.795,94.361 v1(266.573,96.139)
QBB_N: T5.4 U2.15 | length 7.1
  Top Layer w0.254: T5.4@274.07,92.075 276.987,92.075 277.876,91.186 278.638,91.186 279.019,91.567 279.045,91.567 U2.15@279.045,92.485 U2.15@279.045,93.12
QBB_P: T5.6 U2.16 | length 6.6
  Top Layer w0.254: T5.6@274.07,97.155 274.32,97.155 278.384,93.091 U2.16@278.384,92.496
SPSDO: U1.58 U6.1 | length 56.4
  Top Layer w0.254: U1.58@208.25,75.16 208.25,68.991 220.726,56.515 248.92,56.515 ; U6.1@248.33,54.92 248.33,55.925 248.92,56.515 ; 251.46,56.515 248.92,56.515
VCC: 
VDDM: C32.1 C35.1 C72.1 C75.1 C78.1 L8.1 R26.2 U2.7 U2.12 | length 16.7
  Top Layer w0.4: U2.12@280.995,92.485 280.995,94.305 v1@281.051,94.361 ; v1(281.026,94.437) 281.051,94.463 C75.1@281.051,97.79 ; U2.7@282.296,86.741 282.296,85.09 v1(282.473,84.912) ; v1@282.448,84.836 v1@282.575,84.836 ; v1@282.448,84.963 v1@282.512,84.9 ; C78.1@284.215,83.82 283.591,83.82 v1@282.575,84.836 ; R26.2@284.226,87.63 284.215,87.619 C32.1@284.215,85.725 283.326,84.836 v1@282.575,84.836 ; v1(287.909,95.885) L8.1@289.395,95.885
  Bottom Layer w0.4: v1@280.924,94.488 C72.1@282.776,94.488
VDDMIN: C28.1 L8.2 | length 8.2
  Top Layer w0.5: L8.2@290.83,95.885 L8.2@290.995,95.885 293.878,95.885 294.005,95.758 C28.1@294.005,90.985 C28.1@294.005,90.805
pads on no net: T1.5 T2.5 T3.5 T4.2 T5.2 T5.5 T6.2 T6.5 U1.8 U1.9 U1.33 U1.53 U1.57 U2.17 U4.6 U6.4 U6.6 U6.8 U6.10 U7.6 U7.7 U7.9 U7.10 U8.3 U8.4

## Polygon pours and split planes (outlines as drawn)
DGND on Bottom Layer "Top Layer-No Net" (solid, pour order 30): 158.75,151.13 158.75,160.02 202.565,160.02 202.565,139.7 212.09,130.175 212.09,115.57 208.28,111.76 208.28,92.71 211.455,92.71 211.455,70.485 217.805,64.135 298.45,64.135 298.45,34.29 289.56,34.29 289.56,25.4 158.75,25.4 158.75,34.29 149.86,34.29 149.86,151.13
AGND on Bottom Layer "Top Layer-No Net" (solid, pour order 18): 246.38,160.02 289.56,160.02 289.56,151.13 298.45,151.13 298.45,114.935 269.875,114.935 269.875,64.77 217.805,64.77 212.09,70.485 212.09,92.71 215.9,92.71 215.9,97.155 219.075,97.155 227.965,106.045 238.76,106.045 255.905,123.19 255.905,137.16 246.38,137.16
CGND on Bottom Layer "Top Layer-No Net" (solid, pour order 22): 203.2,160.02 203.2,139.7 212.725,130.175 212.725,115.57 208.915,111.76 208.915,93.345 215.265,93.345 215.265,97.79 219.075,97.79 227.965,106.68 238.76,106.68 255.27,123.19 255.27,136.525 245.745,136.525 245.745,160.02
DGND2 on Bottom Layer "Top Layer-No Net" (solid, pour order 23): 298.45,114.3 270.51,114.3 270.51,64.77 298.45,64.77
DGND on Top Layer "Top Layer-No Net" (solid, pour order 29): 158.75,151.13 158.75,160.02 202.565,160.02 202.565,139.7 212.09,130.175 212.09,115.57 208.28,111.76 208.28,92.71 211.455,92.71 211.455,70.485 217.805,64.135 298.45,64.135 298.45,34.29 289.56,34.29 289.56,25.4 158.75,25.4 158.75,34.29 149.86,34.29 149.86,151.13
AGND on Top Layer "Top Layer-No Net" (solid, pour order 17): 246.38,160.02 289.56,160.02 289.56,151.13 298.45,151.13 298.45,114.935 269.875,114.935 269.875,64.77 217.805,64.77 212.09,70.485 212.09,92.71 215.9,92.71 215.9,97.155 219.075,97.155 227.965,106.045 238.76,106.045 255.905,123.19 255.905,137.16 246.38,137.16
CGND on Top Layer "Top Layer-No Net" (solid, remove dead copper, pour order 20): 203.2,160.02 203.2,139.7 212.725,130.175 212.725,115.57 208.915,111.76 208.915,93.345 215.265,93.345 215.265,97.79 219.075,97.79 227.965,106.68 238.76,106.68 255.27,123.19 255.27,136.525 245.745,136.525 245.745,160.02
DGND2 on Top Layer "Top Layer-No Net" (solid, pour order 24): 298.45,114.3 270.51,114.3 270.51,64.77 298.45,64.77
DGND on Ground "Top Layer-No Net" (solid, pour order 31): 158.75,151.13 158.75,160.02 202.565,160.02 202.565,139.7 212.09,130.175 212.09,115.57 208.28,111.76 208.28,92.71 211.455,92.71 211.455,70.485 217.805,64.135 298.45,64.135 298.45,34.29 289.56,34.29 289.56,25.4 158.75,25.4 158.75,34.29 149.86,34.29 149.86,151.13
AGND on Ground "Top Layer-No Net" (solid, pour order 19): 246.38,160.02 289.56,160.02 289.56,151.13 298.45,151.13 298.45,114.935 269.875,114.935 269.875,64.77 217.805,64.77 212.09,70.485 212.09,92.71 215.9,92.71 215.9,97.155 219.075,97.155 227.965,106.045 238.76,106.045 255.905,123.19 255.905,137.16 246.38,137.16
CGND on Ground "Top Layer-No Net" (solid, pour order 26): 203.2,160.02 245.745,160.02 245.745,136.525 255.27,136.525 255.27,123.19 238.76,106.68 227.965,106.68 219.075,97.79 215.265,97.79 215.265,93.345 208.915,93.345 208.915,111.76 212.725,115.57 212.725,130.175 203.2,139.7
DGND2 on Ground "Top Layer-No Net" (solid, pour order 27): 298.45,114.3 270.51,114.3 270.51,64.77 298.45,64.77
DVDD on POwer "Top Layer-No Net" (solid, pour order 32): 158.75,151.13 158.75,160.02 202.565,160.02 202.565,139.7 212.09,130.175 212.09,115.57 208.28,111.76 208.28,92.71 211.455,92.71 211.455,70.485 217.805,64.135 298.45,64.135 298.45,34.29 289.56,34.29 289.56,25.4 158.75,25.4 158.75,34.29 149.86,34.29 149.86,151.13
AVDD on POwer "Top Layer-No Net" (solid, pour order 21): 246.38,160.02 289.56,160.02 289.564,151.072 298.45,151.13 298.45,114.935 269.875,114.935 269.875,64.77 217.805,64.77 212.09,70.485 212.09,92.71 215.9,92.71 215.9,97.155 219.075,97.155 227.965,106.045 238.76,106.045 255.905,123.19 255.905,137.16 246.38,137.16
CLKVDD on POwer "Top Layer-No Net" (solid, pour order 28): 203.2,160.02 245.745,160.02 245.745,136.525 255.27,136.525 255.27,123.19 238.76,106.68 227.965,106.68 219.075,97.79 215.265,97.79 215.265,93.345 208.915,93.345 208.915,111.76 212.725,115.57 212.725,130.175 203.2,139.7
VDDM on POwer "Top Layer-No Net" (solid, pour order 25): 298.45,114.3 270.51,114.3 270.51,64.77 298.45,64.77

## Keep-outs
Keep-Out Layer:
  the board outline again, w0.254

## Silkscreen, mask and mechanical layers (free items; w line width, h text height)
Top Overlay:
  drawing of 188 lines, arcs and shapes, not listed
  text "CGND" at 232.029,157.48 h1.52
  text "AVDD" at 253.746,157.48 h1.52
  text "DGND" at 188.849,157.353 h1.52
  text "CLKVDD" at 209.169,157.353 h1.52
  text "AGND" at 275.336,157.353 h1.52
  text "DVDD" at 167.513,157.226 h1.52
  text "JP11" at 223.139,136.703 h1
  text "JP9" at 180.238,136.601 h1
  text "JP10" at 266.217,136.601 h1
  text "JP3" at 194.158,131.877 h1
  text "JP25" at 200.711,131.851 h1
  text "GND" at 217.043,130.302 h1
  text "CLKVDD" at 220.853,130.302 h1
  text "GND" at 173.736,130.175 h1
  text "DVDD" at 178.435,130.175 h1
  text "GND" at 262.763,130.175 h1
  text "AVDD" at 267.462,130.175 h1
  text "DATA-A" at 150.876,127.127 h1
  text "JP41" at 214.706,125.451 h1
  text "15" at 157.099,124.587 h1
  text "JP2" at 223.495,123.698 h1
  text "JP24" at 196.901,123.114 h1
  text "14" at 157.099,122.047 h1
  text "13" at 157.099,119.507 h1
  text "JP33" at 196.901,118.618 h1
  text "JP1" at 231.267,117.602 h1 r90
  text "12" at 157.099,116.967 h1
  text "11" at 157.099,114.427 h1
  text "JP12" at 189.941,114.122 h1
  text "JP39" at 197.028,114.122 h1
  text "10" at 157.099,111.887 h1
  text "JP22" at 231.267,111.887 h1 r90
  text "MODULATED" at 287.02,111.125 h1.2
  text "9" at 157.099,109.347 h1
  text "OUTPUT" at 288.925,108.966 h1.2
  text "8" at 157.099,106.807 h1
  text "JP28" at 239.268,105.791 h1
  text "JP35" at 232.41,105.283 h1
  text "7" at 157.099,104.267 h1
  text "6" at 157.099,101.727 h1
  text "JP15" at 260.604,101.092 h1
  text "5" at 157.099,99.187 h1
  text "W11" at 292.989,98.478 h1
  text "JP8" at 260.564,97.917 h1
  text "4" at 157.099,96.647 h1
  text "JP13" at 260.604,94.742 h1
  text "3" at 157.099,94.107 h1
  text "VDDM" at 297.231,93.98 h1 r90
  text "2" at 157.099,91.567 h1
  text "JP37" at 232.41,90.678 h1
  text "JP4" at 239.776,90.043 h1
  text "1" at 157.099,89.027 h1
  text "JP29" at 239.268,88.062 h1
  text "JP36" at 232.41,86.868 h1
  text "0" at 157.099,86.487 h1
  text "W12" at 292.76,84.988 h1
  text "JP14" at 260.564,83.312 h1
  text "GND" at 297.231,81.661 h1 r90
  text "JP17" at 260.564,80.137 h1
  text "J1" at 156.972,78.232 h1
  text "JP6" at 160.706,77.546 h1
  text "JP16" at 260.564,76.962 h1
  text "FSADJ1" at 223.266,74.676 h1
  text "JP38" at 232.766,73.482 h1
  text "JP30" at 239.395,72.263 h1
  text "DGND" at 155.448,70.518 h1 r90
  text "JP32" at 182.245,69.596 h1
  text "FSADJ2" at 227.076,69.596 h1
  text "JP27" at 161.417,69.037 h1
  text "LOCAL OSC" at 286.385,69.012 h1.2
  text "AD[15:0]" at 152.908,67.945 h1 r90
  text "INPUT" at 289.56,67.056 h1.2
  text "JP31" at 182.499,65.278 h1
  text "REFIO" at 223.774,64.389 h1
  text "JP26" at 182.372,60.706 h1
  text "JP47" at 250.927,58.242 h1
  text "RESET" at 227.965,58.039 h1
  text "JP46" at 171.399,56.921 h1
  text "JP34" at 176.073,56.921 h1
  text "DGND" at 280.238,55.397 h1
  text "CSB" at 280.238,52.883 h1
  text "CLK" at 280.238,50.394 h1
  text "SDI" at 280.238,47.676 h1
  text "SDO" at 280.238,45.161 h1
  text "JP40" at 171.399,43.078 h1
  text "JP5" at 176.403,43.028 h1
  text "DGND" at 280.238,42.621 h1
  text "SPI PORT" at 282.194,40.132 h1
  text "J2" at 232.232,34.519 h1
  text "15" at 185.928,34.163 h1 r90
  text "14" at 188.468,34.163 h1 r90
  text "13" at 191.008,34.163 h1 r90
  text "12" at 193.548,34.163 h1 r90
  text "11" at 196.088,34.163 h1 r90
  text "10" at 198.628,34.163 h1 r90
  text "9" at 201.168,34.163 h1 r90
  text "8" at 203.708,34.163 h1 r90
  text "7" at 206.248,34.163 h1 r90
  text "6" at 208.788,34.163 h1 r90
  text "5" at 211.328,34.163 h1 r90
  text "4" at 213.868,34.163 h1 r90
  text "3" at 216.408,34.163 h1 r90
  text "2" at 218.948,34.163 h1 r90
  text "1" at 221.488,34.163 h1 r90
  text "0" at 224.028,34.163 h1 r90
  text "EVAL-1273  A044" at 263.398,32.639 h1.52
  text "DGND" at 236.22,31.75 h1
  text "EVAL-1273  A12T" at 263.398,30.099 h1.52
  text "BD[15:0]" at 236.22,29.337 h1
  text "DATA-B" at 182.982,28.753 h1 r90
  text "EVAL-1273  A13T" at 263.398,27.559 h1.52
Mechanical 13:
  the board outline again, w0.254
